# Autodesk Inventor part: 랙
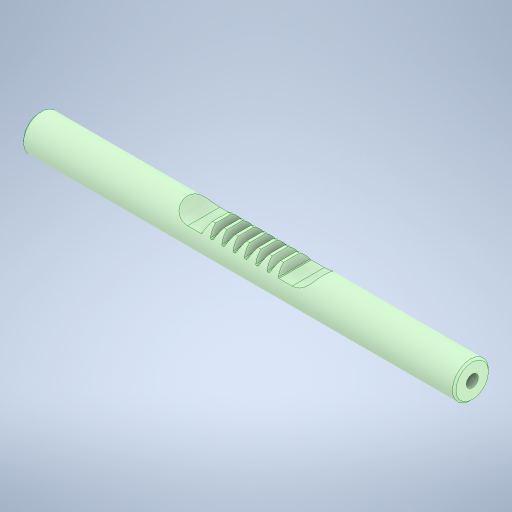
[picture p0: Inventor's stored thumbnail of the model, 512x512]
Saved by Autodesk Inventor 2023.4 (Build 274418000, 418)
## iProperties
Created: 2024-05
Part Number: 랙
Material: 강철, 탄소
Document SubType Name: Modeling
Designer: user
Density: 7.85 g/cm^3
Appearance: 기본값
Author: jhkim
Sending System: Autodesk Inventor 2025
Preprocessor: ST-DEVELOPER v20
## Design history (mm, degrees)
feature "솔리드1"
node "솔리드2"
